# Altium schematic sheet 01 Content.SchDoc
size 297 x 209 mm
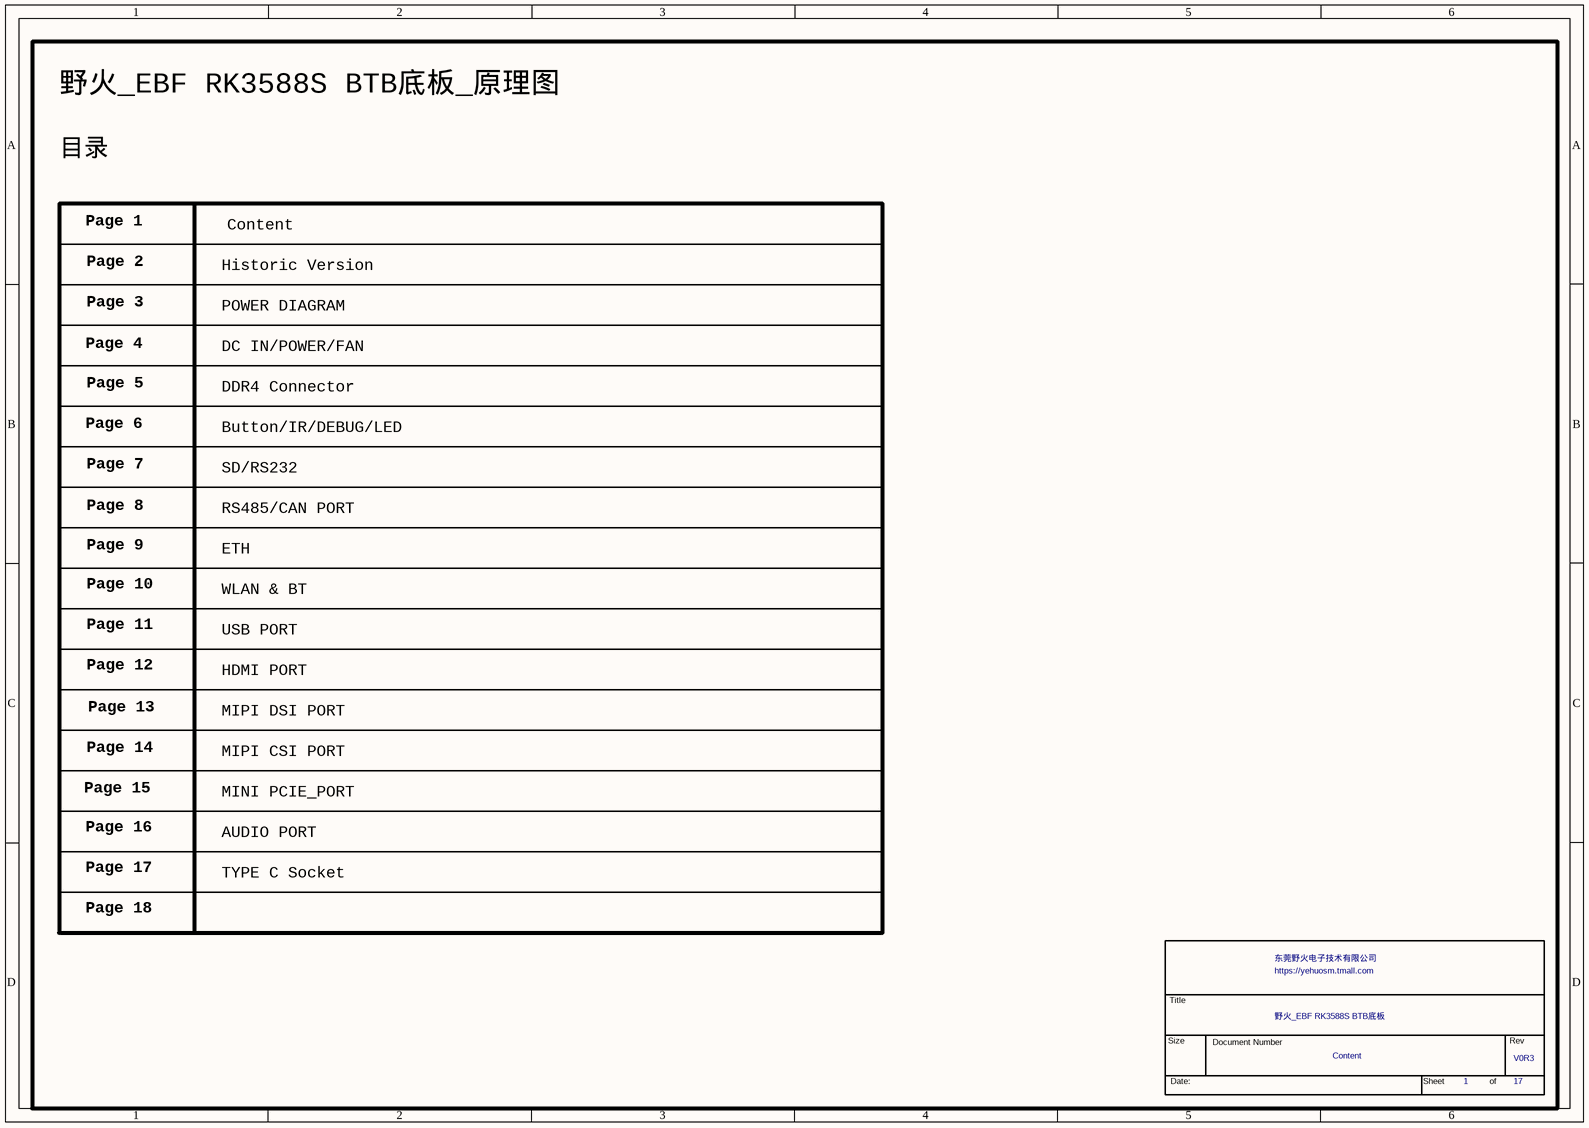
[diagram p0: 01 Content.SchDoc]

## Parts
*  Page Count: 17  Page Number: 1  OrgName: 东莞野火电子技术有限公司  Title: 野火_EBF RK3588S BTB底板  RevCode: V0R3  Doc: Content  (hidden comment: TitleBlock_YHSCH)  (graphical)

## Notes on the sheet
- 野火_EBF RK3588S BTB底板_原理图
- 目录
- Page 1
- Page 2
- Historic Version
- Content
- Page 3
- POWER DIAGRAM
- Page 4
- Page 5
- DC IN/POWER/FAN
- DDR4 Connector
- Page 6
- Page 7
- Button/IR/DEBUG/LED
- SD/RS232
- Page 8
- RS485/CAN PORT
- Page 9
- Page 10
- ETH
- WLAN & BT
- Page 11
- Page 12
- USB PORT
- HDMI PORT
- Page 13
- MIPI DSI PORT
- Page 15
- Page 14
- MIPI CSI PORT
- MINI PCIE_PORT
- Page 17
- Page 16
- AUDIO PORT
- TYPE C Socket
- Page 18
